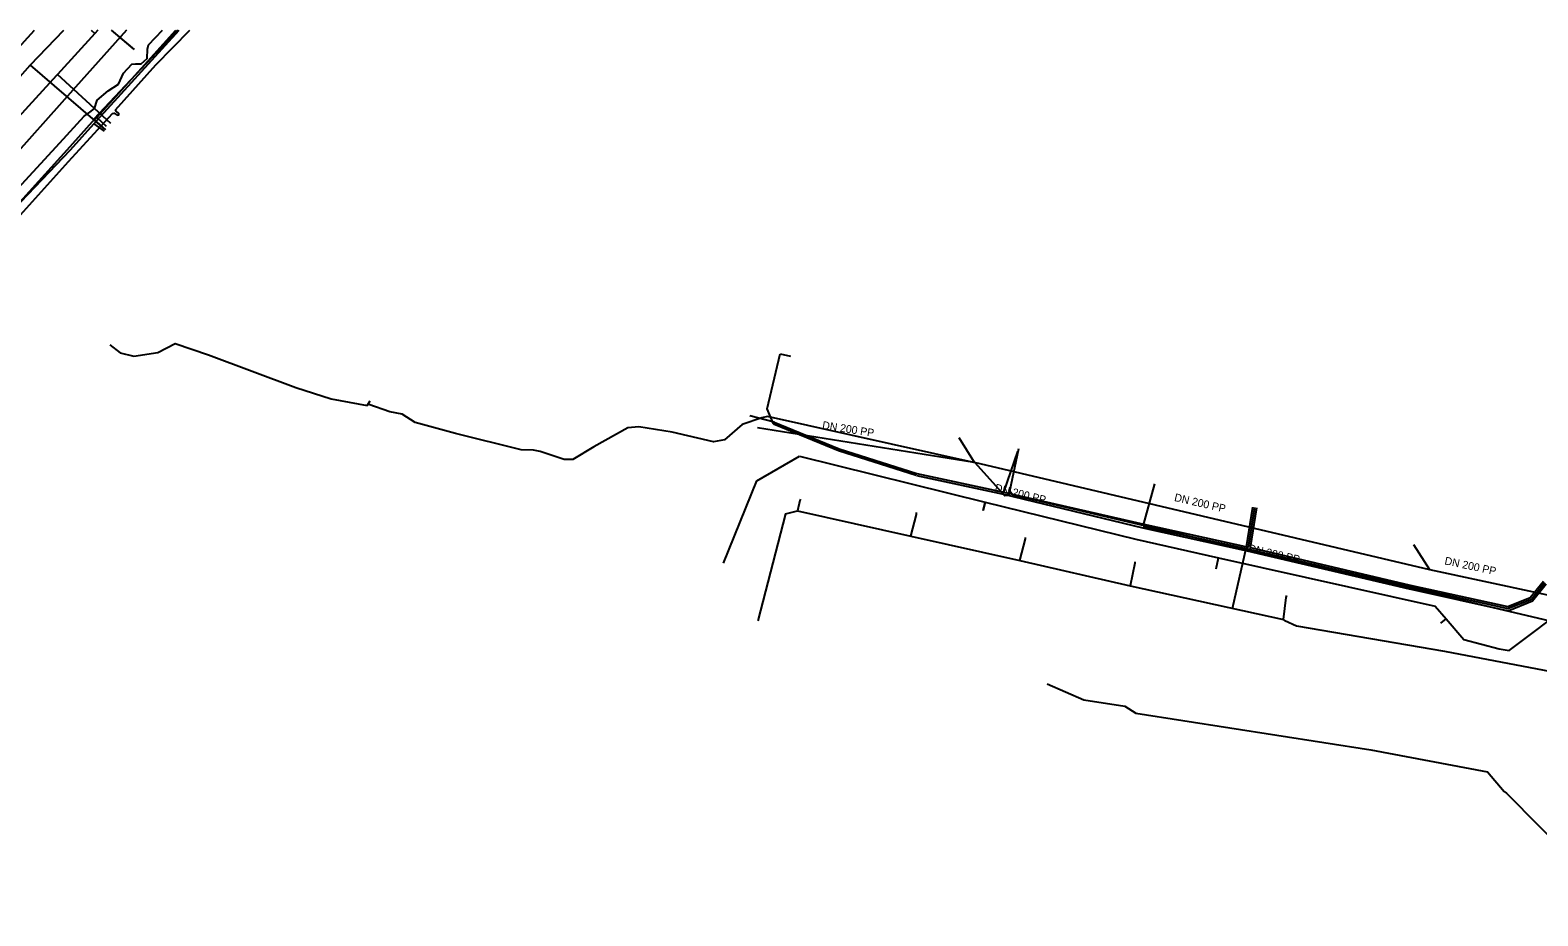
# Model space of a CAD drawing. Extents: x -598932 to -598196, y -1162210 to -1161504.
# Drawn here: x -598627.1 to -598473, y -1161595.8 to -1161505.2 of the extents above; entities that cross this region are included whole.
import ezdxf

# ---------------------------------------------------------------- set-up
doc = ezdxf.new("R2010")
doc.units = 0
for name, color, linetype in [('Vrstva 1', 7, 'Continuous'), ('Vrstva 12', 7, 'Continuous'), ('Vrstva 13', 7, 'Continuous'), ('Vrstva 14', 7, 'Continuous'), ('Vrstva 16', 7, 'Continuous'), ('Vrstva 4', 7, 'Continuous'), ('Vrstva 42', 7, 'Continuous'), ('Vrstva 53', 7, 'Continuous'), ('Vrstva 55', 7, 'Continuous'), ('Vrstva 58', 7, 'Continuous'), ('Vrstva 9', 7, 'Continuous')]:
    doc.layers.add(name, color=color, linetype=linetype)

msp = doc.modelspace()

# ---------------------------------------------------------------- linework, layer by layer
at = {"layer": 'Vrstva 1'}
for p, q in [((-598616.49, -1161507.17), (-598618.821, -1161505.182)), ((-598616.582, -1161507.085), (-598618.819, -1161505.182)), ((-598552.83, -1161551.28), (-598548.47, -1161548.76)), ((-598556.25, -1161559.72), (-598552.83, -1161551.28)), ((-598529.69, -1161554.33), (-598529.474, -1161553.457)), ((-598529.474, -1161553.457), (-598529.69, -1161554.33)), ((-598505.87, -1161560.3), (-598505.614, -1161559.158)), ((-598475.9, -1161568.64), (-598469.148, -1161563.559)), ((-598482.9, -1161565.86), (-598482.354, -1161565.388)), ((-598480.53, -1161567.5), (-598476.93, -1161568.46)), ((-598476.93, -1161568.46), (-598475.9, -1161568.64))]:
    msp.add_line(p, q, dxfattribs=at)
for points in [[(-598548.47, -1161548.76), (-598529.474, -1161553.457), (-598514.09, -1161557.26)], [(-598514.09, -1161557.26), (-598505.614, -1161559.158), (-598483.45, -1161564.12)], [(-598483.45, -1161564.12), (-598482.354, -1161565.388), (-598480.53, -1161567.5)]]:
    msp.add_lwpolyline(points, dxfattribs=at)
at = {"layer": 'Vrstva 12'}
for p, q in [((-598620.64, -1161514.77), (-598611.898, -1161505.182)), ((-598620.64, -1161514.77), (-598619.58, -1161515.5)), ((-598476.18, -1161583.22), (-598465.52, -1161594.05))]:
    msp.add_line(p, q, dxfattribs=at)
for points in [[(-598636.77, -1161516.26), (-598636.41, -1161515.89), (-598635.76, -1161515.14), (-598626.718, -1161505.182)], [(-598648.55, -1161545.71), (-598646.17, -1161542.42), (-598633.92, -1161528.82), (-598623.03, -1161517.41), (-598620.64, -1161514.77)], [(-598523.15, -1161572.06), (-598519.4, -1161573.7), (-598515.19, -1161574.34), (-598514.08, -1161575.06), (-598490.04, -1161578.81), (-598478.1, -1161581.04), (-598476.42, -1161583.05), (-598476.18, -1161583.22)]]:
    msp.add_lwpolyline(points, dxfattribs=at)
at = {"layer": 'Vrstva 13'}
msp.add_lwpolyline([(-598612.067, -1161505.182), (-598620.64, -1161514.28), (-598619.45, -1161515.35)], dxfattribs=at)
at = {"layer": 'Vrstva 14'}
msp.add_lwpolyline([(-598617.291, -1161505.182), (-598622.51, -1161511), (-598630.03, -1161519.46), (-598631.77, -1161521.4), (-598638.33, -1161528.72), (-598641.39, -1161532.13), (-598649.743, -1161541.467), (-598653.67, -1161545.72), (-598657.75, -1161550.15), (-598669.17, -1161562.84), (-598679.31, -1161574.09), (-598691.06, -1161587.14), (-598694.57, -1161591.13), (-598698.516, -1161595.586), (-598699.098, -1161595.784)], dxfattribs=at)
at = {"layer": 'Vrstva 16'}
msp.add_line((-598627.139, -1161508.748), (-598619.534, -1161515.322), dxfattribs=at)
msp.add_lwpolyline([(-598704.416, -1161593.94), (-598704.189, -1161593.693), (-598703.474, -1161593.488), (-598701.717, -1161591.566), (-598698.378, -1161587.844), (-598697.83, -1161587.234), (-598690.41, -1161578.978), (-598683.551, -1161571.298), (-598669.685, -1161555.829), (-598662.143, -1161547.6), (-598661.142, -1161546.517), (-598659.095, -1161544.324), (-598657.824, -1161542.963), (-598645.462, -1161529.118), (-598642.814, -1161526.234), (-598634.193, -1161516.718), (-598632.805, -1161515.147), (-598627.139, -1161508.748), (-598623.719, -1161505.182)], dxfattribs=at)
at = {"layer": 'Vrstva 42'}
for p, q in [((-598551.793, -1161543.919), (-598550.466, -1161538.283)), ((-598550.466, -1161538.283), (-598549.379, -1161538.518)), ((-598551.07, -1161545.27), (-598553.54, -1161544.622)), ((-598551.121, -1161545.463), (-598551.793, -1161543.919)), ((-598551.146, -1161545.455), (-598544.486, -1161548.185)), ((-598551.07, -1161545.27), (-598544.41, -1161548)), ((-598544.41, -1161548), (-598536.47, -1161550.53)), ((-598544.471, -1161548.191), (-598536.531, -1161550.721)), ((-598527.56, -1161552.46), (-598526.16, -1161548.3)), ((-598536.512, -1161550.725), (-598527.604, -1161552.655)), ((-598536.47, -1161550.53), (-598527.56, -1161552.46)), ((-598527.604, -1161552.655), (-598513.356, -1161556.108)), ((-598527.56, -1161552.46), (-598513.26, -1161555.72)), ((-598513.313, -1161555.913), (-598512.12, -1161551.59)), ((-598502.56, -1161558.07), (-598501.91, -1161554.01)), ((-598502.365, -1161558.116), (-598501.713, -1161554.042)), ((-598513.26, -1161555.72), (-598502.56, -1161558.07)), ((-598513.356, -1161556.108), (-598502.708, -1161558.446)), ((-598513.313, -1161555.913), (-598502.641, -1161558.257)), ((-598502.708, -1161558.446), (-598486.111, -1161562.329)), ((-598502.641, -1161558.257), (-598486.066, -1161562.135)), ((-598502.365, -1161558.116), (-598486.02, -1161561.94)), ((-598486.02, -1161561.94), (-598476.04, -1161564.15)), ((-598473.75, -1161563.22), (-598472.4, -1161561.55)), ((-598473.625, -1161563.385), (-598472.246, -1161561.678)), ((-598473.505, -1161563.553), (-598472.106, -1161561.822)), ((-598486.106, -1161562.331), (-598476.005, -1161564.568)), ((-598486.063, -1161562.135), (-598476.023, -1161564.358)), ((-598476.04, -1161564.15), (-598473.75, -1161563.22)), ((-598476.023, -1161564.358), (-598473.625, -1161563.385)), ((-598476.005, -1161564.568), (-598473.505, -1161563.553))]:
    msp.add_line(p, q, dxfattribs=at)
msp.add_lwpolyline([(-598637.604, -1161535.299), (-598637.77, -1161535.15), (-598637.9, -1161535.01), (-598637.83, -1161534.76), (-598632.8, -1161529.31), (-598628.76, -1161524.74), (-598623.23, -1161518.61), (-598618.72, -1161513.7), (-598618.56, -1161513.69), (-598618.242, -1161513.873), (-598618.093, -1161513.845), (-598618.086, -1161513.694), (-598618.362, -1161513.461), (-598618.421, -1161513.33), (-598614.3, -1161508.74), (-598610.834, -1161505.182)], dxfattribs=at)
at = {"layer": 'Vrstva 53'}
for p, q in [((-598592.7, -1161543.58), (-598592.362, -1161543.107)), ((-598526.97, -1161552.35), (-598526.058, -1161547.97)), ((-598526.69, -1161552.71), (-598526.97, -1161552.35))]:
    msp.add_line(p, q, dxfattribs=at)
for points in [[(-598629.08, -1161523.48), (-598628.79, -1161521.78), (-598624.12, -1161516.7), (-598621.64, -1161513.97), (-598621.03, -1161513.56), (-598620.57, -1161513.19), (-598620.3, -1161512.34), (-598619.16, -1161511.38), (-598618.13, -1161510.71), (-598617.59, -1161509.59), (-598616.75, -1161508.65), (-598616.38, -1161508.63), (-598615.79, -1161508.63), (-598615.2, -1161508.08), (-598615.16, -1161507.12), (-598615.03, -1161506.7), (-598613.605, -1161505.182)], [(-598618.987, -1161537.376), (-598617.95, -1161538.18), (-598616.56, -1161538.54), (-598614.09, -1161538.17), (-598612.32, -1161537.25), (-598608.9, -1161538.39), (-598599.97, -1161541.72), (-598596.37, -1161542.91), (-598592.7, -1161543.58)], [(-598551.74, -1161544.72), (-598552.34, -1161544.83), (-598554.32, -1161545.52), (-598556.13, -1161547.08), (-598557.27, -1161547.31), (-598561.5, -1161546.29), (-598564.9, -1161545.76), (-598566.04, -1161545.85), (-598569.49, -1161547.82), (-598571.66, -1161549.09), (-598572.55, -1161549.1), (-598574.99, -1161548.3), (-598575.68, -1161548.16), (-598576.93, -1161548.13), (-598583.66, -1161546.45), (-598587.78, -1161545.32), (-598589.1, -1161544.48), (-598590.36, -1161544.24), (-598592.5, -1161543.48)], [(-598526.97, -1161552.35), (-598527.07, -1161552.78), (-598527.49, -1161552.81), (-598530.51, -1161549.44), (-598551.74, -1161544.72)], [(-598467.49, -1161561.86), (-598471.845, -1161565.591), (-598526.69, -1161552.71)]]:
    msp.add_lwpolyline(points, dxfattribs=at)
at = {"layer": 'Vrstva 55'}
for p, q in [((-598548.45, -1161553.3), (-598548.68, -1161554.37)), ((-598548.37, -1161553.16), (-598548.45, -1161553.3)), ((-598502.757, -1161558.038), (-598502.107, -1161553.978)), ((-598549.89, -1161554.66), (-598552.73, -1161565.62)), ((-598549.89, -1161554.66), (-598548.68, -1161554.37)), ((-598548.68, -1161554.37), (-598537.07, -1161556.96)), ((-598537.07, -1161556.96), (-598536.52, -1161554.73)), ((-598536.52, -1161554.73), (-598536.51, -1161554.51)), ((-598537.07, -1161556.96), (-598525.95, -1161559.43)), ((-598525.95, -1161559.43), (-598525.37, -1161557.21)), ((-598525.37, -1161557.21), (-598525.35, -1161557.08)), ((-598504.178, -1161564.334), (-598502.757, -1161558.038)), ((-598525.95, -1161559.43), (-598514.67, -1161562.02)), ((-598514.17, -1161559.71), (-598514.67, -1161562.02)), ((-598514.17, -1161559.58), (-598514.17, -1161559.71)), ((-598514.67, -1161562.02), (-598498.98, -1161565.48)), ((-598498.98, -1161565.48), (-598498.69, -1161563.23)), ((-598498.69, -1161563.23), (-598498.63, -1161563.01)), ((-598498.83, -1161565.56), (-598498.98, -1161565.48)), ((-598498.83, -1161565.56), (-598497.65, -1161566.11)), ((-598497.65, -1161566.11), (-598482.52, -1161568.71)), ((-598482.52, -1161568.71), (-598466.58, -1161571.73))]:
    msp.add_line(p, q, dxfattribs=at)
at = {"layer": 'Vrstva 58'}
msp.add_line((-598620.34, -1161514.12), (-598619.39, -1161515.01), dxfattribs=at)
for points in [[(-598629.08, -1161523.48), (-598628.79, -1161521.78), (-598624.12, -1161516.7), (-598621.64, -1161513.97), (-598621.03, -1161513.56), (-598620.57, -1161513.19), (-598620.3, -1161512.34), (-598619.16, -1161511.38), (-598618.13, -1161510.71), (-598617.59, -1161509.59), (-598616.75, -1161508.65), (-598616.38, -1161508.63), (-598615.79, -1161508.63), (-598615.2, -1161508.08), (-598615.16, -1161507.12), (-598615.03, -1161506.7), (-598613.605, -1161505.182)], [(-598620.34, -1161514.12), (-598614.47, -1161507.64), (-598612.264, -1161505.182)], [(-598635.14, -1161530.75), (-598633.49, -1161529), (-598632.7, -1161528.05), (-598631.76, -1161526.68), (-598623.38, -1161517.41), (-598620.77, -1161514.52), (-598620.34, -1161514.12)]]:
    msp.add_lwpolyline(points, dxfattribs=at)
at = {"layer": 'Vrstva 9'}
for p, q in [((-598620.903, -1161505.182), (-598620.53, -1161505.523)), ((-598618.886, -1161514.726), (-598624.364, -1161509.714)), ((-598552.77, -1161545.83), (-598530.6, -1161549.39)), ((-598532.164, -1161546.864), (-598530.6, -1161549.39)), ((-598530.6, -1161549.39), (-598484.03, -1161560.35)), ((-598485.674, -1161557.802), (-598484.03, -1161560.35))]:
    msp.add_line(p, q, dxfattribs=at)
for points in [[(-598620.218, -1161505.182), (-598620.53, -1161505.523), (-598620.544, -1161505.538), (-598624.364, -1161509.714), (-598624.46, -1161509.819), (-598630.561, -1161516.487), (-598630.571, -1161516.497), (-598631.425, -1161517.431), (-598631.513, -1161517.527), (-598642.32, -1161529.34)], [(-598484.03, -1161560.35), (-598472.929, -1161562.744), (-598469.148, -1161563.559), (-598468.17, -1161563.77)]]:
    msp.add_lwpolyline(points, dxfattribs=at)

# ---------------------------------------------------------------- texts
at = {"layer": 'Vrstva 12'}
for rotation, p in [(351, (-598546.189, -1161545.955)), (347, (-598510.2, -1161553.333)), (348, (-598482.556, -1161559.82))]:
    msp.add_text('DN 200 PP', height=0.8, rotation=rotation, dxfattribs=at).set_placement(p)
at = {"layer": 'Vrstva 4'}
for rotation, p in [(346, (-598528.566, -1161552.345)), (347, (-598502.626, -1161558.531))]:
    msp.add_text('DN 200 PP', height=0.8, rotation=rotation, dxfattribs=at).set_placement(p)

doc.saveas('drawing.dxf')
